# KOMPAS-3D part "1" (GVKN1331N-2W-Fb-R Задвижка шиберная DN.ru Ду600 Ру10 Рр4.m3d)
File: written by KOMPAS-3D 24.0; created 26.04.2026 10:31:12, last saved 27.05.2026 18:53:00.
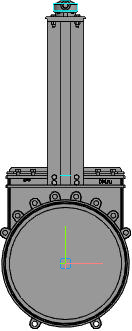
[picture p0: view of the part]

Document properties: Автор: R2D2; Полное имя файла: E:\Работа\Зайцев\АУТСОРС\Даня\GVKN1331N-2W-Fb-R Задвижка шиберная DN.ru Ду400-600 Ру4-6\исходные материалы\DN600\GVKN1331N-2W-Fb-R Задвижка шиберная DN.ru Ду600 Ру10 Рр4.m3d

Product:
- Component [standard]: Hexagon head screw ISO 4017 - М10 x 25  | qty 4  | Масса: 0.026096; Рассекать на разрезах: no; source file: C:\Program Files\ASCON\KOMPAS-3D v24\Libs\PolynomLib\DATA\vault\methods\kompas\3d\PLib_Bolt_1_ISO_1100.m3d
- Body: Тело 4  | qty 1
    Масса: 235.783912
- Body: Тело 5  | qty 1
    Масса: 235.783912
- Body: Тело 6  | qty 1
    Масса: 19.978776
- Body: Тело 7  | qty 1
    Масса: 235.783912
- Body: Тело 8  | qty 1
    Масса: 5.600139
- Body: Тело 12  | qty 1
    Масса: 5.600139
- Component [standard]: (unnamed)  | qty 4  | Масса: 0.1215; Рассекать на разрезах: no; additional columns: М16-6gx55; Болт; ГОСТ 7805-70
- Component [standard]: Гайка М16-6H ГОСТ 5915-70  | qty 4  | Масса: 0.03761; Рассекать на разрезах: no; source file: C:\Program Files\ASCON\KOMPAS-3D v24\Libs\PolynomLib\DATA\vault\methods\kompas\3d\PLib_Nut_OST92_900.m3d
- Component [standard]: Болт М18-6gx30 ГОСТ 7805-70  | qty 1  | Масса: 0.1143; Рассекать на разрезах: no; source file: C:\Program Files\ASCON\KOMPAS-3D v24\Libs\PolynomLib\DATA\vault\methods\kompas\3d\PLib_Bolt_1_900.m3d
- Component [standard]: Болт М18-6gx30 ГОСТ 7805-70  | qty 7  | Масса: 0.1143; Рассекать на разрезах: no
- Component [standard]: Болт М16-6gx30 ГОСТ 7805-70  | qty 1  | Масса: 0.08324; Рассекать на разрезах: no; source file: C:\Program Files\ASCON\KOMPAS-3D v24\Libs\PolynomLib\DATA\vault\methods\kompas\3d\PLib_Bolt_1_900.m3d
- Component [standard]: Болт М16-6gx30 ГОСТ 7805-70  | qty 7  | Масса: 0.08324; Рассекать на разрезах: no
- Body: Тело 14  | qty 1
    Масса: 235.783912
- Part/product: 1
    Масса: 18.2
    Раздел спецификации: Прочие изделия
    Примечание: D050-23732

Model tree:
1. Смещенная плоскость:2
2. Корпус
3. Элемент вращения:1
     Угол 1 = 360
4. Ушко  (with: Ребро.Элемент вращения:1)
5. Элемент выдавливания:5
6. Диск  (with: Ребро.Элемент вращения:1)
7. Элемент выдавливания:3
     Расстояние 1 = 10
8. Скругление:10  (with: Ребро.Элемент выдавливания:5)
     Радиус = 5
9. Скругление:11  (with: Ребро.Элемент выдавливания:5)
     Радиус = 2
10. Массив по концентрической сетке:7  (with: Элемент выдавливания:5, Скругление:10, Скругление:11, Грань.Элемент вращения:1)  (10 pattern instances)
11. Корпус штока
12. Элемент выдавливания:6  (with: Грань.Элемент вращения:1)
13. Эскиз:3  (with: Грань.Элемент выдавливания:5, Ребро.Скругление:11)
14. Элемент выдавливания:12
15. Массив по концентрической сетке:9  (with: Элемент выдавливания:12, Эскиз:3, Грань.Элемент вращения:1)  (17 pattern instances)
     Шаг 2 = 360
16. Зеркальный массив:2
17. Экземпляр ( 1 )
18. Экземпляр ( 2 )  (with: Массив по концентрической сетке:9, Экземпляр ( 1 ), Элемент выдавливания:12)
19. Экземпляр ( 3 )  (with: Элемент выдавливания:12)
20. Экземпляр ( 4 )  (with: Элемент выдавливания:12)
21. Экземпляр ( 5 )  (with: Элемент выдавливания:12)
22. Экземпляр ( 6 )  (with: Элемент выдавливания:12)
23. Экземпляр ( 7 )  (with: Элемент выдавливания:12)
24. Экземпляр ( 8 )  (with: Элемент выдавливания:12)
25. Экземпляр ( 9 )  (with: Элемент выдавливания:12)
26. Экземпляр ( 10 )  (with: Элемент выдавливания:12)
27. Экземпляр ( 12 )  (with: Элемент выдавливания:12)
28. Экземпляр ( 13 )  (with: Элемент выдавливания:12)
29. Экземпляр ( 14 )  (with: Элемент выдавливания:12)
30. Экземпляр ( 15 )  (with: Элемент выдавливания:12)
31. Экземпляр ( 18 )  (with: Элемент выдавливания:12)
32. Экземпляр ( 19 )  (with: Элемент выдавливания:12)
33. Экземпляр ( 20 )  (with: Элемент выдавливания:12)
34. Эскиз:24  (with: Грань.Элемент вращения:1, Ребро.Элемент вращения:1)
35. Элемент выдавливания:36
     Расстояние 2 = 2
36. Зеркальный массив:4  (with: Экземпляр ( 1 ), Экземпляр ( 2 ), Элемент выдавливания:36)
37. Резиновое уплотнение
38. Элемент выдавливания:4
39. Скругление:2  (with: Грань.Элемент выдавливания:4)
     Радиус = 2
40. Скругление:4  (with: Ребро.Элемент выдавливания:6)
     Радиус = 2
41. фланец  (with: Грань.Элемент выдавливания:6, Ребро.Элемент выдавливания:6)
42. Элемент выдавливания:13
     Расстояние 2 = 15
43. Скругление:12  (with: Ребро.Элемент выдавливания:13)
     Радиус = 10
44. Массив по сетке:1  (with: Элемент выдавливания:13, Эскиз:4, Скругление:12)  (2 pattern instances)
     Шаг 1 = 50; Угол раствора = 90
45. Эскиз:5  (with: Грань.Элемент выдавливания:6, Ребро.Элемент выдавливания:13)  (labels: Ребро.Элемент выдавливания:13.Экземпляр ( 2, 1 ))
46. Элемент выдавливания:14  (with: Грань.Элемент вращения:1)
     Расстояние 1 = 29.75; Смещение 1 = 1
47. Эскиз:6  (with: Грань.Элемент выдавливания:6, Ребро.Элемент выдавливания:13, Ребро.Элемент выдавливания:14)  (labels: Ребро.Элемент выдавливания:13.Экземпляр ( 2, 1 ))
48. Элемент выдавливания:15  (with: Грань.Элемент вращения:1)
     Расстояние 1 = 29.75; Смещение 1 = 1
49. Эскиз:7  (with: Вершина.Элемент выдавливания:14, Ребро.Элемент выдавливания:14)  (labels: Грань.Элемент выдавливания:13.Экземпляр ( 2, 1 ))
50. Элемент выдавливания:16
51. Эскиз:8  (with: Ребро.Элемент выдавливания:15)  (labels: Грань.Элемент выдавливания:13.Экземпляр ( 2, 1 ))
52. Элемент выдавливания:17  (with: Грань.Элемент выдавливания:16)
     Расстояние 1 = 890
53. Смещенная плоскость:3
54. Эскиз:9  (with: Грань.Элемент выдавливания:16, Вершина.Элемент выдавливания:17, Ребро.Элемент выдавливания:16, Ребро.Элемент выдавливания:17)
55. Элемент выдавливания:18
     Расстояние 2 = 15
56. Скругление:13  (with: Ребро.Элемент выдавливания:16, Ребро.Элемент выдавливания:17)
     Радиус = 15
57. Эскиз:10  (with: Грань.Элемент выдавливания:18, Ребро.Скругление:13, Ребро.Элемент выдавливания:18, Ребро.Элемент выдавливания:17)
58. Элемент выдавливания:19
     Расстояние 1 = 10
59. Эскиз:11  (with: Грань.Элемент выдавливания:13, Ребро.Элемент выдавливания:13)
60. Элемент выдавливания:20
     Расстояние 1 = 10
61. Эскиз:12  (with: Грань.Элемент выдавливания:20, Ребро.Элемент выдавливания:13, Ребро.Элемент выдавливания:17, Вершина.Элемент выдавливания:17, Вершина.Элемент выдавливания:18)
62. Элемент выдавливания:21
     Расстояние 1 = 10
63. Фаска:1  (with: Ребро.Элемент выдавливания:21)
     Угол = 60; Длина 1 = 20; Длина 2 = 34.641
64. Фаска:2  (with: Ребро.Элемент выдавливания:21)
     Угол = 60; Длина 1 = 20; Длина 2 = 34.641
65. Эскиз:13  (with: Грань.Элемент выдавливания:13)
66. Элемент выдавливания:22  (with: Грань.Элемент выдавливания:21)
     Расстояние 1 = 45; Смещение 1 = 25
67. Скругление:14  (with: Ребро.Элемент выдавливания:22)
     Радиус = 20
68. Эскиз:14  (with: Грань.Элемент выдавливания:21, Ребро.Элемент выдавливания:22, Ребро.Элемент выдавливания:21)
69. Элемент выдавливания:23
     Расстояние 1 = 30
70. Эскиз:15  (with: Грань.Элемент выдавливания:23, Ребро.Элемент выдавливания:23)
71. Элемент выдавливания:24  (with: Грань.Элемент выдавливания:19)
     Расстояние 1 = 790
72. Эскиз:16  (with: Грань.Элемент выдавливания:19, Ребро.Элемент выдавливания:24)
73. Элемент выдавливания:25  (with: Грань.Элемент выдавливания:18)
     Расстояние 2 = 25
74. Массив по концентрической сетке:10  (with: Элемент выдавливания:25, Эскиз:16, Грань.Элемент выдавливания:24)  (4 pattern instances)
     Шаг 2 = 360
75. Эскиз:17  (with: Грань.Элемент выдавливания:19, Ребро.Элемент выдавливания:24, Ребро.Элемент выдавливания:19)
76. Элемент выдавливания:26
     Расстояние 1 = 25
77. ИСО фланец  (with: Грань.Элемент выдавливания:26, Ребро.Элемент выдавливания:26)
78. Элемент выдавливания:7
     Расстояние 1 = 10
79. отв. исо фланца  (with: Грань.Элемент выдавливания:7, Ребро.Элемент выдавливания:7)
80. Элемент выдавливания:27  (with: Грань.Элемент выдавливания:7)
     Расстояние 2 = 10
81. Массив по концентрической сетке:11  (with: Элемент выдавливания:27, Грань.Элемент выдавливания:7)  (4 pattern instances)
     Шаг 2 = 360
82. Эскиз:18  (with: Грань.Элемент выдавливания:7, Ребро.Элемент выдавливания:7)
83. Элемент выдавливания:28
     Расстояние 1 = 2
84. Смещенная плоскость:4  (with: Грань.Элемент выдавливания:7)
     Расстояние = 0.5
85. Эскиз:19  (with: Ребро.Элемент выдавливания:7)
86. Элемент выдавливания:29
     Расстояние 1 = 30
87. Эскиз:20  (with: Ребро.Элемент выдавливания:29)
88. Элемент выдавливания:30
     Расстояние 2 = 5
89. Элемент по сечениям:1  (with: Грань.Элемент выдавливания:30, Грань.Элемент выдавливания:29)
90. Скругление:15  (with: Ребро.Элемент выдавливания:30)
     Радиус = 5
91. ЛЕЙБЛ
92. Элемент выдавливания:31  (with: Грань.Элемент выдавливания:6)
     Расстояние 1 = 34.75; Смещение 1 = 1
93. Нормальная плоскость:1  (with: Грань.Элемент выдавливания:29)
94. Эскиз:21
95. Элемент выдавливания:32
     Расстояние 1 = 100
96. Фаска:3  (with: Ребро.Элемент выдавливания:32)
     Угол = 45; Длина 1 = 10; Длина 2 = 10
97. Эскиз:22  (with: Грань.Элемент выдавливания:32, Ребро.Фаска:3)
98. Элемент выдавливания:33
     Расстояние 1 = 20
99. Массив по концентрической сетке:2  (with: Грань.Элемент выдавливания:7)  (4 pattern instances)
     Шаг 2 = 360
100. Массив по концентрической сетке:3  (with: Грань.Элемент выдавливания:26)  (4 pattern instances)
     Шаг 2 = 360
101. Эскиз:23  (with: Грань.Элемент выдавливания:16, Ребро.Элемент выдавливания:16)
102. Элемент выдавливания:34
103. Зеркальный массив:3  (with: Экземпляр ( 1 ), Экземпляр ( 2 ), Элемент выдавливания:34)
104. Эскиз:25  (labels: Грань.Элемент выдавливания:5.Экземпляр ( 1, 13 ); Ребро.Элемент выдавливания:12.Экземпляр ( 1, 13 ))
105. Элемент выдавливания:37
106. Массив по концентрической сетке:12  (with: Элемент выдавливания:37, Эскиз:25, Грань.Элемент выдавливания:7, Грань.Элемент выдавливания:19, Грань.Элемент выдавливания:18, Грань.Элемент выдавливания:21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)  (labels: Ребро.Элемент выдавливания:27.Экземпляр ( 1, 4 ); Грань.Элемент выдавливания:25.Экземпляр ( 1, 2 ); Грань.Элемент выдавливания:34.Экземпляр ( 2 ))  (11 pattern instances)
     Шаг 2 = 360

Expressions: v30-20; v161-20; D2-5; H1/3; D/2-D1/2; L/2+5; 360/n/2; D1*0.85; H1-H1/3-50; id3-id4*2; DS*2; D1/4+10; D2-20; v4384_v161-20
Referenced files in C:\Program Files\ASCON\KOMPAS-3D v24\Libs\PolynomLib\DATA\vault\Methods\Kompas\3D\: PLib_Bolt_1_ISO_1100.m3d, PLib_Bolt_1_900.m3d, PLib_Nut_OST92_900.m3d
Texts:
  BOSimple***PART:f114febc-ab7b-6638-bb5e-15f0e2e47160***SHORTLOC:A259_7B16EF33AB1642D2[16;1,5;25;10;-;Undefined]
  BOSimple***PART:d5043757-7383-cfe0-2773-bdcfb0c19ea2***SHORTLOC:Root±30±20±10±80±10±©{}30±©{BASE}130±30[Нет;Без покрытия;Без указания материала;55;16;24;2;-]
  BOSimple***PART:17b45fe1-43c8-f41a-5df4-ae57481e6c3b***SHORTLOC:Root±30±10±20±©{}110±10±50±60[Нет;Без покрытия;Без указания материала;-;16;2;24]
  BOSimple***PART:58fea51c-4c27-65e8-868c-b0420730e5b8***SHORTLOC:Root±30±20±10±80±10±©{}30±©{BASE}130±30[Нет;Без покрытия;Без указания материала;30;18;27;2,5;-]
  BOSimple***PART:296a4829-a4b6-4e05-4821-ac6adc08aeaf***SHORTLOC:Root±30±20±10±80±10±©{}30±©{BASE}130±30[Нет;Без покрытия;Без указания материала;30;16;24;2;-]
  GOST 26.020 Pr3
  var3D
  ширина затвора по металлу
  Диаметр исо фланца
  id4
  Диуметр отверстия  исо фланца
  id3
  ось отв. исо фланца
  id5
  ds1
  Hexagon head screw ISO 4017 - М10 x 25 (1)
  hole1
  hole2
  Деталь (1)
  Гайка М16-6H ГОСТ 5915-70 (1)
  bcut1
  hcut1
  cut1
  Болт М18-6gx30 ГОСТ 7805-70 (1)
  Болт М18-6gx30 ГОСТ 7805-70 (2)
  Болт М18-6gx30 ГОСТ 7805-70 (3)
  Болт М18-6gx30 ГОСТ 7805-70 (4)
  Болт М18-6gx30 ГОСТ 7805-70 (5)
  Болт М18-6gx30 ГОСТ 7805-70 (6)
  Болт М18-6gx30 ГОСТ 7805-70 (7)
  Болт М18-6gx30 ГОСТ 7805-70 (8)
  Болт М16-6gx30 ГОСТ 7805-70 (1)
  Болт М16-6gx30 ГОСТ 7805-70 (2)
  Болт М16-6gx30 ГОСТ 7805-70 (3)
  Болт М16-6gx30 ГОСТ 7805-70 (4)
  Болт М16-6gx30 ГОСТ 7805-70 (5)
  Болт М16-6gx30 ГОСТ 7805-70 (6)
  Болт М16-6gx30 ГОСТ 7805-70 (7)
  Болт М16-6gx30 ГОСТ 7805-70 (8)
  Plane. Начало координат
